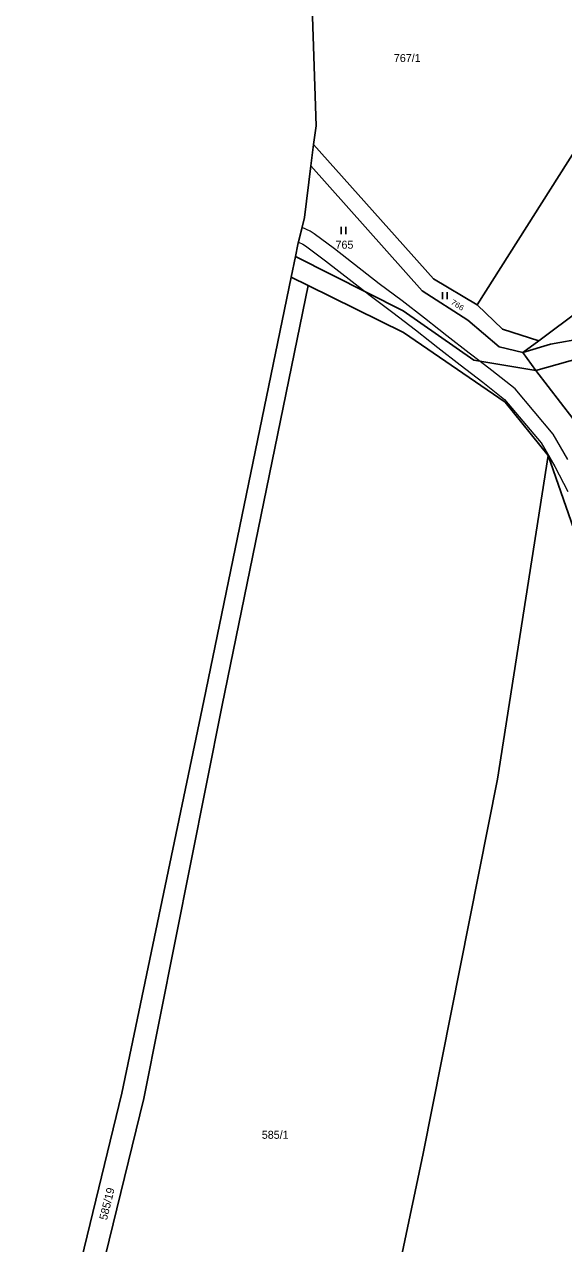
# Model space of a CAD drawing. Extents: x -701211 to -698780, y -1014269 to -1012378.
# Drawn here: x -701144.4 to -701029.9, y -1012933.2 to -1012674.3 of the extents above; entities that cross this region are included whole.
import ezdxf
from ezdxf.enums import TextEntityAlignment as Align

# ---------------------------------------------------------------- set-up
doc = ezdxf.new("R2010")
doc.units = 0
doc.header["$LTSCALE"] = 0.68
for name, color, linetype, lineweight in [('1', 7, 'Continuous', 25), ('13', 7, 'Continuous', 13), ('3', 7, 'Continuous', 25)]:
    doc.layers.add(name, color=color, linetype=linetype, lineweight=lineweight)
doc.layers.add('2', color=7, linetype='Continuous')

msp = doc.modelspace()

# ---------------------------------------------------------------- linework, layer by layer
at = {"layer": '1'}
for p, q in [((-701083.47, -1012664.89), (-701082.38, -1012695.85)), ((-701048.22, -1012733.88), (-701008.69, -1012671.43)), ((-701082.38, -1012695.85), (-701082.97, -1012699.83)), ((-701083.52, -1012704.35), (-701082.97, -1012699.83)), ((-701057.47, -1012728.4), (-701082.97, -1012699.83)), ((-701084.86, -1012715.35), (-701083.52, -1012704.35)), ((-701059.9, -1012730.92), (-701083.52, -1012704.35)), ((-701084.86, -1012715.35), (-701086.28, -1012721.05)), ((-701086.81, -1012723.62), (-701086.28, -1012721.05)), ((-701087.71, -1012727.98), (-701086.81, -1012723.62)), ((-701063.96, -1012735.16), (-701086.81, -1012723.62)), ((-701106.29, -1012818.01), (-701087.71, -1012727.98)), ((-701084.12, -1012729.79), (-701087.71, -1012727.98)), ((-701048.22, -1012733.88), (-701057.47, -1012728.4)), ((-701102.39, -1012818.88), (-701084.12, -1012729.79)), ((-701063.87, -1012739.74), (-701084.12, -1012729.79)), ((-701050.2, -1012737.12), (-701059.9, -1012730.92)), ((-701063.96, -1012735.16), (-701048.96, -1012745.67)), ((-701042.84, -1012739.09), (-701048.22, -1012733.88)), ((-701026.15, -1012734.82), (-701035.16, -1012741.52)), ((-701063.87, -1012739.74), (-701042.25, -1012754.55)), ((-701042.84, -1012739.09), (-701035.16, -1012741.52)), ((-701035.16, -1012741.52), (-701038.53, -1012744.03)), ((-701038.53, -1012744.03), (-701032.65, -1012742.22)), ((-701014.71, -1012741.85), (-701035.74, -1012747.8)), ((-701035.74, -1012747.8), (-701048.96, -1012745.67)), ((-701035.74, -1012747.8), (-701038.53, -1012744.03)), ((-701025.26, -1012761.42), (-701035.74, -1012747.8)), ((-701042.25, -1012754.55), (-701033.16, -1012765.88)), ((-701033.16, -1012765.88), (-701043.92, -1012834.59)), ((-701033.16, -1012765.88), (-701022.57, -1012796.35)), ((-701123.69, -1012901.28), (-701106.29, -1012818.01)), ((-701119, -1012902.41), (-701102.39, -1012818.88)), ((-701043.92, -1012834.59), (-701059.71, -1012914.09)), ((-701123.69, -1012901.28), (-701144.36, -1012986.22)), ((-701139.82, -1012987.38), (-701119, -1012902.41))]:
    msp.add_line(p, q, dxfattribs=at)
for points in [[(-701038.53, -1012744.03), (-701043.55, -1012742.78), (-701050.2, -1012737.12)], [(-701032.65, -1012742.22), (-701018.33, -1012739.7), (-701006.05, -1012737.17)], [(-701059.71, -1012914.09), (-701076.93, -1012996.09), (-701094.33, -1013065.72)]]:
    msp.add_lwpolyline(points, dxfattribs=at)
at = {"layer": '13'}
for points in [[(-701028.98, -1012766.71), (-701032.07, -1012761.35), (-701040.18, -1012751.73), (-701045.11, -1012747.82), (-701047.62, -1012745.89), (-701049.89, -1012744.14), (-701054.65, -1012740.44), (-701056.37, -1012739.14), (-701059.38, -1012736.72), (-701064.18, -1012733.01), (-701069, -1012729.4), (-701078.54, -1012722.02), (-701082.84, -1012718.83), (-701083.7, -1012718.23), (-701085.39, -1012717.48), (-701086.17, -1012720.6)], [(-701086.17, -1012720.6), (-701085.24, -1012721.01), (-701084.68, -1012721.39), (-701080.44, -1012724.54), (-701071.92, -1012731.14), (-701070.92, -1012731.92), (-701066.1, -1012735.53), (-701061.34, -1012739.2), (-701058.31, -1012741.64), (-701056.57, -1012742.94), (-701051.83, -1012746.64), (-701047.05, -1012750.3), (-701042.4, -1012754.01), (-701034.67, -1012763.17), (-701031.74, -1012768.23), (-701028.96, -1012773.52)]]:
    msp.add_lwpolyline(points, dxfattribs=at)
at = {"layer": '3'}
for p, q in [((-701077.081, -1012718.85), (-701077.081, -1012717.35)), ((-701076.08, -1012718.85), (-701076.08, -1012717.35)), ((-701055.581, -1012732.7), (-701055.581, -1012731.2)), ((-701054.58, -1012732.7), (-701054.58, -1012731.2))]:
    msp.add_line(p, q, dxfattribs=at)

# ---------------------------------------------------------------- texts
at = {"layer": '2'}
for s, p in [('767/1', (-701063.07, -1012682.325)), ('585/1', (-701091.11, -1012910.985))]:
    msp.add_text(s, height=1.7, dxfattribs=at).set_placement(p, align=Align.CENTER)
msp.add_text('765', height=1.7, dxfattribs=at).set_placement((-701078.3, -1012721.975))
at = {"layer": '2', "width": 1.15}
msp.add_text('766', height=1.14, rotation=327, dxfattribs=at).set_placement((-701052.6964, -1012734.4113), align=Align.CENTER)
at = {"layer": '2'}
msp.add_text('585/19', height=1.7, rotation=76, dxfattribs=at).set_placement((-701126.857, -1012928.362))

doc.saveas('drawing.dxf')
